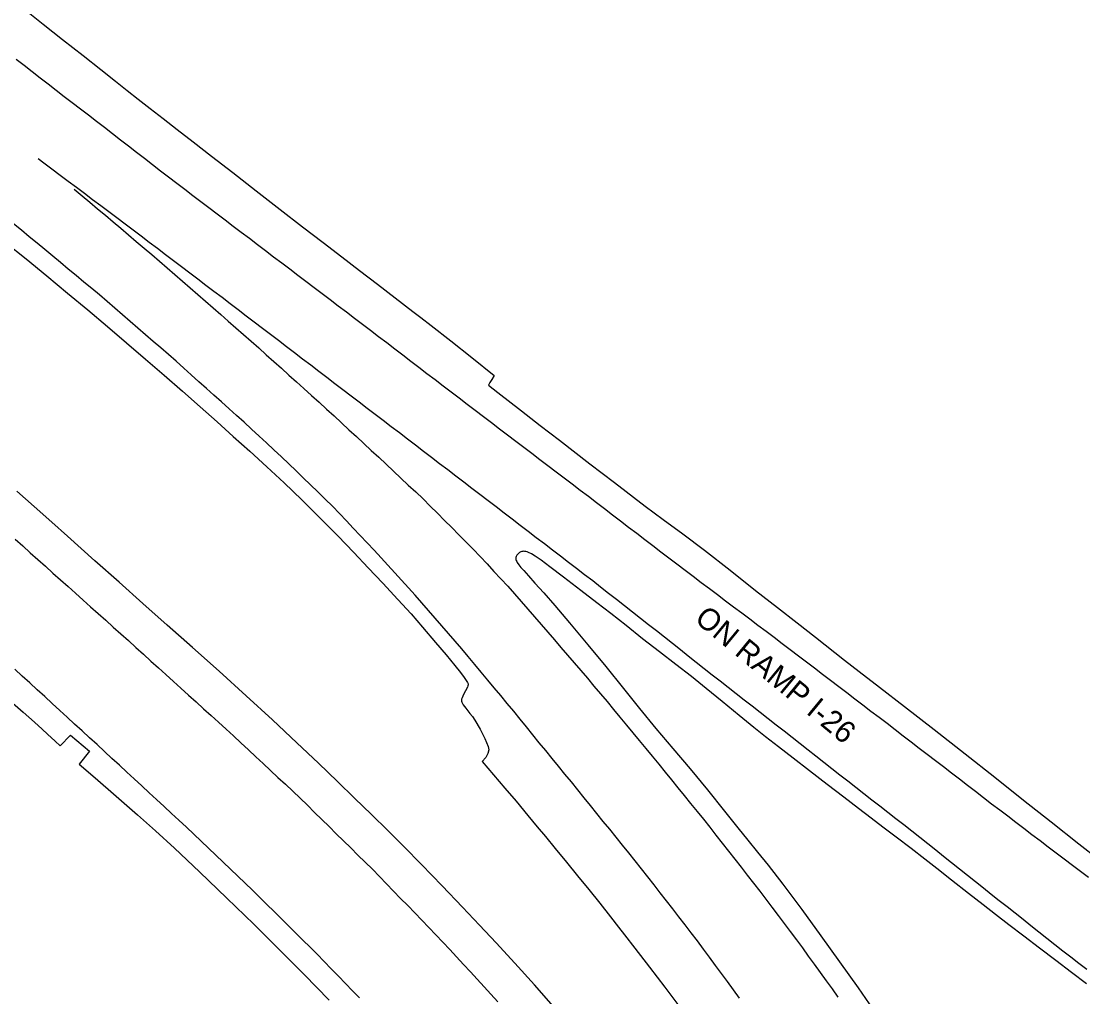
# Model space of a CAD drawing. Extents: x 1948091 to 1975253, y 787267 to 823306.
# Drawn here: x 1968847.6 to 1969109.2, y 799121.5 to 799361.9 of the extents above; entities that cross this region are included whole.
import ezdxf

# ---------------------------------------------------------------- set-up
doc = ezdxf.new("R2010")
doc.units = 0
for name, color, linetype in [('RD_EX_Pavement_Markings', 7, 'Continuous'), ('RD_EX_Road', 7, 'Continuous'), ('RD_TX_RoadID', 7, 'Continuous')]:
    doc.layers.add(name, color=color, linetype=linetype)

msp = doc.modelspace()

# ---------------------------------------------------------------- linework, layer by layer
at = {"layer": 'RD_EX_Pavement_Markings'}
for points in [[(1968846.31, 799352.62), (1968848.29, 799351.09), (1968850.27, 799349.55), (1968852.24, 799348.02), (1968854.22, 799346.49), (1968856.19, 799344.96), (1968858.17, 799343.43), (1968860.15, 799341.9), (1968862.13, 799340.37), (1968864.1, 799338.84), (1968866.08, 799337.32), (1968868.06, 799335.79), (1968870.04, 799334.26), (1968872.02, 799332.73), (1968874, 799331.21), (1968875.98, 799329.68), (1968877.96, 799328.15), (1968879.94, 799326.62), (1968881.92, 799325.1), (1968883.9, 799323.57), (1968885.88, 799322.05), (1968887.87, 799320.53), (1968889.86, 799319.02), (1968891.85, 799317.51), (1968893.84, 799316), (1968895.84, 799314.49), (1968897.83, 799312.98), (1968899.82, 799311.47), (1968901.81, 799309.95), (1968903.8, 799308.44), (1968905.79, 799306.93), (1968907.78, 799305.42), (1968909.77, 799303.91), (1968911.77, 799302.4), (1968913.76, 799300.88), (1968915.75, 799299.37), (1968917.74, 799297.86), (1968919.73, 799296.35), (1968921.72, 799294.84), (1968923.71, 799293.33), (1968925.71, 799291.82), (1968927.7, 799290.3), (1968929.69, 799288.79), (1968931.68, 799287.28), (1968933.67, 799285.77), (1968935.66, 799284.26), (1968937.65, 799282.74), (1968939.63, 799281.22), (1968941.62, 799279.7), (1968943.61, 799278.18), (1968945.59, 799276.67), (1968947.58, 799275.15), (1968949.56, 799273.63), (1968951.55, 799272.11), (1968953.54, 799270.59), (1968955.52, 799269.08), (1968957.51, 799267.56), (1968959.49, 799266.04), (1968961.48, 799264.52), (1968963.47, 799263.01), (1968965.46, 799261.5), (1968967.45, 799259.99), (1968969.44, 799258.47), (1968971.43, 799256.96), (1968973.42, 799255.45), (1968975.41, 799253.93), (1968977.4, 799252.42), (1968979.39, 799250.91), (1968981.38, 799249.39), (1968983.37, 799247.88), (1968985.36, 799246.37), (1968987.35, 799244.85), (1968989.34, 799243.33), (1968991.32, 799241.82), (1968993.31, 799240.3), (1968995.3, 799238.78), (1968997.28, 799237.26), (1968999.27, 799235.74), (1969001.26, 799234.23), (1969003.24, 799232.71), (1969005.23, 799231.19), (1969007.22, 799229.67), (1969009.2, 799228.16), (1969011.19, 799226.65), (1969013.19, 799225.14), (1969015.19, 799223.64), (1969017.18, 799222.13), (1969019.18, 799220.63), (1969021.18, 799219.12), (1969023.17, 799217.62), (1969025.17, 799216.11), (1969027.16, 799214.61), (1969029.16, 799213.1), (1969031.16, 799211.6), (1969033.15, 799210.09), (1969035.15, 799208.59), (1969037.14, 799207.07), (1969039.13, 799205.56), (1969041.12, 799204.04), (1969043.1, 799202.53), (1969045.09, 799201.01), (1969047.08, 799199.5), (1969049.07, 799197.98), (1969051.06, 799196.46), (1969053.05, 799194.95), (1969055.03, 799193.43), (1969057.02, 799191.92), (1969059.01, 799190.4), (1969061, 799188.89), (1969062.98, 799187.36), (1969064.96, 799185.84), (1969066.94, 799184.32), (1969068.93, 799182.79), (1969070.91, 799181.27), (1969072.89, 799179.74), (1969074.87, 799178.22), (1969076.85, 799176.7), (1969078.84, 799175.17), (1969080.82, 799173.65), (1969082.8, 799172.13), (1969084.78, 799170.6), (1969086.76, 799169.08), (1969088.75, 799167.56), (1969090.74, 799166.05), (1969092.73, 799164.54), (1969094.72, 799163.02), (1969096.71, 799161.51), (1969098.7, 799160), (1969100.69, 799158.48), (1969102.68, 799156.97), (1969104.67, 799155.45), (1969106.66, 799153.95), (1969108.67, 799152.46), (1969110.68, 799150.96)], [(1969110.25, 799128.18), (1969108.26, 799129.7), (1969106.29, 799131.24), (1969104.32, 799132.77), (1969102.35, 799134.31), (1969100.38, 799135.85), (1969098.41, 799137.39), (1969096.45, 799138.94), (1969094.5, 799140.5), (1969092.54, 799142.06), (1969090.59, 799143.62), (1969088.63, 799145.17), (1969086.68, 799146.73), (1969084.72, 799148.29), (1969082.76, 799149.85), (1969080.81, 799151.4), (1969078.85, 799152.96), (1969076.9, 799154.52), (1969074.94, 799156.08), (1969072.99, 799157.63), (1969071.03, 799159.19), (1969069.07, 799160.75), (1969067.11, 799162.29), (1969065.14, 799163.83), (1969063.17, 799165.37), (1969061.2, 799166.91), (1969059.23, 799168.45), (1969057.26, 799169.99), (1969055.29, 799171.53), (1969053.32, 799173.07), (1969051.35, 799174.61), (1969049.38, 799176.15), (1969047.41, 799177.69), (1969045.44, 799179.23), (1969043.47, 799180.77), (1969041.5, 799182.31), (1969039.53, 799183.85), (1969037.56, 799185.39), (1969035.59, 799186.92), (1969033.62, 799188.46), (1969031.65, 799190), (1969029.68, 799191.54), (1969027.71, 799193.08), (1969025.74, 799194.62), (1969023.77, 799196.16), (1969021.81, 799197.7), (1969019.84, 799199.25), (1969017.88, 799200.8), (1969015.92, 799202.35), (1969013.96, 799203.91), (1969012, 799205.46), (1969010.04, 799207.01), (1969008.08, 799208.56), (1969006.12, 799210.1), (1969004.15, 799211.65), (1969002.18, 799213.19), (1969000.22, 799214.74), (1968998.25, 799216.28), (1968996.28, 799217.82), (1968994.32, 799219.37), (1968992.35, 799220.91), (1968990.38, 799222.45), (1968988.42, 799224), (1968986.43, 799225.52), (1968984.45, 799227.04), (1968982.46, 799228.56), (1968980.48, 799230.08), (1968978.49, 799231.6), (1968976.51, 799233.12), (1968974.52, 799234.64), (1968972.54, 799236.15), (1968970.55, 799237.67), (1968968.57, 799239.19), (1968966.58, 799240.71), (1968964.6, 799242.23), (1968962.62, 799243.75), (1968960.63, 799245.27), (1968958.65, 799246.79), (1968956.66, 799248.31), (1968954.68, 799249.83), (1968952.69, 799251.35), (1968950.7, 799252.87), (1968948.72, 799254.38), (1968946.73, 799255.9), (1968944.74, 799257.42), (1968942.75, 799258.94), (1968940.77, 799260.45), (1968938.78, 799261.97), (1968936.79, 799263.49), (1968934.81, 799265), (1968932.82, 799266.52), (1968930.83, 799268.04), (1968928.85, 799269.55), (1968926.86, 799271.07), (1968924.87, 799272.59), (1968922.88, 799274.1), (1968920.9, 799275.62), (1968918.91, 799277.14), (1968916.92, 799278.66), (1968914.94, 799280.17), (1968912.95, 799281.69), (1968910.96, 799283.21), (1968908.98, 799284.72), (1968906.99, 799286.24), (1968905, 799287.76), (1968903.01, 799289.27), (1968901.03, 799290.79), (1968899.04, 799292.31), (1968897.05, 799293.82), (1968895.06, 799295.33), (1968893.07, 799296.84), (1968891.07, 799298.35), (1968889.08, 799299.87), (1968887.09, 799301.38), (1968885.1, 799302.89), (1968883.11, 799304.4), (1968881.12, 799305.91), (1968879.12, 799307.42), (1968877.13, 799308.93), (1968875.14, 799310.44), (1968873.15, 799311.95), (1968871.16, 799313.46), (1968869.15, 799314.96), (1968867.15, 799316.46), (1968865.15, 799317.96), (1968863.15, 799319.46), (1968861.15, 799320.95), (1968859.15, 799322.45), (1968857.15, 799323.95), (1968855.14, 799325.45), (1968853.14, 799326.95), (1968851.72, 799328.01)], [(1968860.62, 799320.53), (1968862.54, 799318.93), (1968864.46, 799317.32), (1968866.37, 799315.72), (1968868.29, 799314.11), (1968870.21, 799312.51), (1968872.12, 799310.9), (1968874.03, 799309.29), (1968875.93, 799307.66), (1968877.83, 799306.04), (1968879.73, 799304.41), (1968881.63, 799302.79), (1968883.53, 799301.16), (1968885.43, 799299.54), (1968887.33, 799297.91), (1968889.21, 799296.26), (1968891.09, 799294.61), (1968892.97, 799292.96), (1968894.84, 799291.31), (1968896.72, 799289.66), (1968898.6, 799288.01), (1968900.47, 799286.36), (1968902.35, 799284.71), (1968904.23, 799283.06), (1968906.11, 799281.41), (1968907.97, 799279.74), (1968909.83, 799278.07), (1968911.69, 799276.39), (1968913.54, 799274.72), (1968915.4, 799273.05), (1968917.26, 799271.38), (1968919.12, 799269.7), (1968920.97, 799268.03), (1968922.83, 799266.36), (1968924.67, 799264.66), (1968926.5, 799262.96), (1968928.34, 799261.26), (1968930.17, 799259.56), (1968932, 799257.86), (1968933.83, 799256.16), (1968935.67, 799254.46), (1968937.5, 799252.76), (1968939.32, 799251.05), (1968941.15, 799249.34), (1968942.97, 799247.63), (1968944.8, 799245.92), (1968946.61, 799244.2), (1968948.38, 799242.44), (1968950.15, 799240.67), (1968951.93, 799238.91), (1968953.7, 799237.15), (1968955.45, 799235.36), (1968957.2, 799233.58), (1968958.95, 799231.79), (1968960.7, 799230.01), (1968962.4, 799228.17), (1968964.09, 799226.34), (1968965.78, 799224.5), (1968967.48, 799222.66), (1968969.15, 799220.8), (1968970.79, 799218.91), (1968972.43, 799217.03), (1968974.07, 799215.14), (1968975.71, 799213.26), (1968977.36, 799211.37), (1968978.99, 799209.47), (1968980.61, 799207.57), (1968982.24, 799205.67), (1968983.86, 799203.77), (1968985.49, 799201.87), (1968987.11, 799199.98), (1968988.73, 799198.08), (1968990.36, 799196.18), (1968991.96, 799194.26), (1968993.55, 799192.33), (1968995.14, 799190.4), (1968996.74, 799188.47), (1968998.33, 799186.55), (1968999.92, 799184.62), (1969001.51, 799182.69), (1969003.1, 799180.76), (1969004.69, 799178.83), (1969006.26, 799176.89), (1969007.84, 799174.95), (1969009.41, 799173), (1969010.99, 799171.06), (1969012.56, 799169.12), (1969014.14, 799167.18), (1969015.72, 799165.24), (1969017.28, 799163.29), (1969018.82, 799161.32), (1969020.36, 799159.36), (1969021.9, 799157.39), (1969023.45, 799155.42), (1969024.99, 799153.45), (1969026.53, 799151.48), (1969028.07, 799149.52), (1969029.6, 799147.53), (1969031.1, 799145.54), (1969032.61, 799143.54), (1969034.11, 799141.55), (1969035.62, 799139.55), (1969037.12, 799137.55), (1969038.63, 799135.56), (1969040.12, 799133.55), (1969041.58, 799131.52), (1969043.04, 799129.5), (1969044.5, 799127.47), (1969045.96, 799125.44), (1969047.42, 799123.41), (1969048.88, 799121.38)], [(1969024.59, 799121.15), (1969023.15, 799123.2), (1969021.68, 799125.22), (1969020.19, 799127.23), (1969018.7, 799129.23), (1969017.21, 799131.24), (1969015.71, 799133.25), (1969014.22, 799135.25), (1969012.73, 799137.26), (1969011.21, 799139.24), (1969009.67, 799141.21), (1969008.14, 799143.19), (1969006.6, 799145.16), (1969005.07, 799147.14), (1969003.54, 799149.11), (1969002, 799151.08), (1969000.46, 799153.05), (1968998.89, 799155), (1968997.32, 799156.95), (1968995.75, 799158.89), (1968994.18, 799160.84), (1968992.61, 799162.78), (1968991.04, 799164.73), (1968989.47, 799166.67), (1968987.9, 799168.62), (1968986.33, 799170.56), (1968984.75, 799172.5), (1968983.17, 799174.44), (1968981.59, 799176.37), (1968980.01, 799178.31), (1968978.43, 799180.25), (1968976.85, 799182.18), (1968975.27, 799184.12), (1968973.69, 799186.06), (1968972.11, 799187.99), (1968970.53, 799189.93), (1968968.95, 799191.87), (1968967.35, 799193.8), (1968965.75, 799195.72), (1968964.15, 799197.64), (1968962.55, 799199.56), (1968960.96, 799201.48), (1968959.36, 799203.4), (1968957.76, 799205.32), (1968956.14, 799207.23), (1968954.5, 799209.12), (1968952.87, 799211.01), (1968951.23, 799212.9), (1968949.6, 799214.79), (1968947.96, 799216.68), (1968946.33, 799218.57), (1968944.67, 799220.45), (1968942.99, 799222.3), (1968941.3, 799224.14), (1968939.62, 799225.99), (1968937.94, 799227.84), (1968936.25, 799229.69), (1968934.57, 799231.53), (1968932.86, 799233.36), (1968931.14, 799235.17), (1968929.42, 799236.99), (1968927.7, 799238.8), (1968925.98, 799240.62), (1968924.26, 799242.43), (1968922.47, 799244.17), (1968920.67, 799245.91), (1968918.88, 799247.65), (1968917.08, 799249.39), (1968915.29, 799251.13), (1968913.49, 799252.87), (1968911.68, 799254.6), (1968909.84, 799256.29), (1968908.01, 799257.99), (1968906.17, 799259.68), (1968904.33, 799261.38), (1968902.5, 799263.08), (1968900.64, 799264.75), (1968898.78, 799266.42), (1968896.92, 799268.09), (1968895.06, 799269.76), (1968893.2, 799271.43), (1968891.34, 799273.1), (1968889.48, 799274.78), (1968887.62, 799276.45), (1968885.76, 799278.12), (1968883.88, 799279.76), (1968881.99, 799281.4), (1968880.1, 799283.03), (1968878.21, 799284.67), (1968876.31, 799286.3), (1968874.42, 799287.94), (1968872.53, 799289.57), (1968870.64, 799291.21), (1968868.75, 799292.84), (1968866.85, 799294.47), (1968864.93, 799296.06), (1968863, 799297.66), (1968861.08, 799299.26), (1968859.16, 799300.86), (1968857.23, 799302.45), (1968855.31, 799304.05), (1968853.39, 799305.65), (1968851.47, 799307.25), (1968849.54, 799308.84), (1968847.6, 799310.41), (1968845.65, 799311.99)], [(1968846.06, 799234.27), (1968847.92, 799232.61), (1968849.78, 799230.94), (1968851.64, 799229.27), (1968853.5, 799227.61), (1968855.37, 799225.94), (1968857.23, 799224.27), (1968859.09, 799222.61), (1968860.95, 799220.94), (1968862.81, 799219.27), (1968864.67, 799217.61), (1968866.54, 799215.94), (1968868.4, 799214.28), (1968870.26, 799212.61), (1968872.12, 799210.94), (1968873.98, 799209.28), (1968875.84, 799207.61), (1968877.69, 799205.93), (1968879.54, 799204.25), (1968881.39, 799202.57), (1968883.24, 799200.89), (1968885.09, 799199.21), (1968886.94, 799197.54), (1968888.79, 799195.86), (1968890.64, 799194.18), (1968892.5, 799192.5), (1968894.35, 799190.82), (1968896.2, 799189.14), (1968898.05, 799187.47), (1968899.89, 799185.78), (1968901.71, 799184.07), (1968903.54, 799182.37), (1968905.37, 799180.67), (1968907.2, 799178.97), (1968909.03, 799177.26), (1968910.85, 799175.56), (1968912.68, 799173.86), (1968914.51, 799172.16), (1968916.32, 799170.44), (1968918.1, 799168.69), (1968919.88, 799166.93), (1968921.66, 799165.18), (1968923.44, 799163.43), (1968925.22, 799161.68), (1968927, 799159.92), (1968928.78, 799158.17), (1968930.56, 799156.42), (1968932.33, 799154.66), (1968934.11, 799152.91), (1968935.85, 799151.12), (1968937.6, 799149.33), (1968939.34, 799147.54), (1968941.08, 799145.75), (1968942.83, 799143.96), (1968944.56, 799142.17), (1968946.29, 799140.37), (1968948.02, 799138.57), (1968949.76, 799136.77), (1968951.47, 799134.95), (1968953.17, 799133.12), (1968954.87, 799131.3), (1968956.57, 799129.47), (1968958.28, 799127.64), (1968959.98, 799125.81), (1968961.68, 799123.98), (1968963.35, 799122.13), (1968965.02, 799120.27)], [(1968930.96, 799121.2), (1968929.22, 799122.99), (1968927.48, 799124.78), (1968925.74, 799126.58), (1968923.99, 799128.37), (1968922.25, 799130.16), (1968920.51, 799131.95), (1968918.75, 799133.72), (1968916.98, 799135.48), (1968915.2, 799137.23), (1968913.42, 799138.99), (1968911.64, 799140.75), (1968909.87, 799142.5), (1968908.09, 799144.26), (1968906.31, 799146.01), (1968904.53, 799147.77), (1968902.73, 799149.49), (1968900.92, 799151.22), (1968899.11, 799152.94), (1968897.3, 799154.67), (1968895.5, 799156.39), (1968893.69, 799158.12), (1968891.88, 799159.84), (1968890.07, 799161.57), (1968888.26, 799163.29), (1968886.43, 799164.99), (1968884.6, 799166.68), (1968882.76, 799168.38), (1968880.93, 799170.08), (1968879.09, 799171.77), (1968877.26, 799173.47), (1968875.43, 799175.17), (1968873.59, 799176.86), (1968871.75, 799178.56), (1968869.91, 799180.25), (1968868.08, 799181.94), (1968866.24, 799183.63), (1968864.4, 799185.32), (1968862.56, 799187.01), (1968860.72, 799188.71), (1968858.88, 799190.4), (1968857.04, 799192.09), (1968855.19, 799193.78), (1968853.35, 799195.46), (1968851.5, 799197.15), (1968849.66, 799198.84), (1968847.82, 799200.52), (1968845.97, 799202.21)]]:
    msp.add_lwpolyline(points, dxfattribs=at)
at = {"layer": 'RD_EX_Road'}
for points in [[(1968849.26, 799364.16), (1968852.94, 799361.25), (1968857.77, 799357.44), (1968862.82, 799353.46), (1968867.16, 799350.04), (1968870.78, 799347.18), (1968873.68, 799344.88), (1968876.37, 799342.77), (1968879.31, 799340.46), (1968882.53, 799337.96), (1968886.01, 799335.25), (1968889.94, 799332.21), (1968894.5, 799328.67), (1968899.68, 799324.64), (1968905.5, 799320.13), (1968911.42, 799315.54), (1968916.9, 799311.3), (1968921.95, 799307.4), (1968926.56, 799303.85), (1968930.96, 799300.48), (1968935.34, 799297.11), (1968939.7, 799293.76), (1968944.06, 799290.42), (1968946.02, 799288.89), (1968948.57, 799286.93), (1968953.42, 799283.14), (1968958.6, 799279.05), (1968964.11, 799274.66), (1968963.55, 799273.61), (1968963.08, 799272.88), (1968962.72, 799272.22), (1968965.08, 799270.46), (1968970.89, 799265.91), (1968975.51, 799262.31), (1968980.21, 799258.68), (1968987.7, 799252.88), (1968993.78, 799248.22), (1969001.37, 799242.45), (1969005.81, 799239.11), (1969010.62, 799235.58), (1969016.02, 799231.53), (1969022.28, 799226.62), (1969028.55, 799221.65), (1969034, 799217.4), (1969038.86, 799213.63), (1969043.32, 799210.1), (1969050.49, 799204.45), (1969054.08, 799201.68), (1969059.09, 799197.83), (1969065.32, 799193.02), (1969072.59, 799187.38), (1969080.22, 799181.4), (1969087.56, 799175.59), (1969094.62, 799169.97), (1969101.4, 799164.59), (1969108.25, 799159.19), (1969113.1, 799155.39)], [(1968843.57, 799307.52), (1968848.75, 799303.37), (1968853.89, 799299.15), (1968858.98, 799294.95), (1968863.99, 799290.78), (1968868.83, 799286.68), (1968873.52, 799282.67), (1968878.16, 799278.67), (1968882.77, 799274.67), (1968887.28, 799270.75), (1968891.67, 799266.91), (1968895.84, 799263.21), (1968899.83, 799259.61), (1968903.9, 799255.94), (1968908.08, 799252.14), (1968912.35, 799248.16), (1968916.69, 799243.97), (1968921.12, 799239.59), (1968925.56, 799235.09), (1968929.55, 799230.97), (1968933.09, 799227.24), (1968936.7, 799223.4), (1968940.38, 799219.45), (1968943.64, 799215.84), (1968946.49, 799212.57), (1968949.69, 799208.83), (1968952.27, 799205.79), (1968954.45, 799203.15), (1968955.86, 799201.38), (1968956.76, 799200.18), (1968957.25, 799199.47), (1968957.55, 799198.97), (1968957.64, 799198.78), (1968957.69, 799198.6), (1968957.69, 799198.37), (1968957.65, 799198.1), (1968957.56, 799197.79), (1968957.06, 799196.9), (1968956.57, 799195.99), (1968956.21, 799195.2), (1968956.12, 799194.88), (1968956.09, 799194.63), (1968956.11, 799194.38), (1968956.18, 799194.11), (1968956.31, 799193.8), (1968956.5, 799193.46), (1968957.12, 799192.59), (1968958.14, 799191.35), (1968958.76, 799190.58), (1968959.38, 799189.67), (1968960.66, 799187.43), (1968961.8, 799185.11), (1968962.64, 799183.2), (1968962.8, 799182.33), (1968962.61, 799181.42), (1968962.06, 799180.47), (1968961.15, 799179.48), (1968966.76, 799172.94), (1968969.54, 799169.68), (1968972.46, 799166.18), (1968974.75, 799163.41), (1968976.76, 799160.96), (1968979.15, 799158.06), (1968981.94, 799154.67), (1968984.72, 799151.28), (1968987.44, 799147.94), (1968990.16, 799144.53), (1968992.81, 799141.16), (1968994.81, 799138.63), (1968996.3, 799136.75), (1968998.82, 799133.51), (1969002.44, 799128.78), (1969006.22, 799123.83), (1969010.16, 799118.6)], [(1968978.78, 799119.12), (1968974.05, 799124.47), (1968969.23, 799129.77), (1968964.63, 799134.75), (1968960.55, 799139.13), (1968956.33, 799143.61), (1968951.29, 799148.87), (1968946.22, 799154.11), (1968941.89, 799158.5), (1968937.91, 799162.47), (1968933.87, 799166.45), (1968929.75, 799170.46), (1968925.52, 799174.57), (1968920.86, 799179.03), (1968915.5, 799184.11), (1968909.51, 799189.71), (1968903, 799195.7), (1968896.31, 799201.76), (1968889.78, 799207.56), (1968883.5, 799213.11), (1968877.54, 799218.42), (1968871.68, 799223.66), (1968865.72, 799228.98), (1968858.98, 799234.98), (1968855.06, 799238.48), (1968850.78, 799242.3), (1968846.48, 799246.13)], [(1969110.13, 799124.68), (1969106.42, 799127.47), (1969102.55, 799130.41), (1969098.55, 799133.46), (1969094.68, 799136.43), (1969091.01, 799139.25), (1969087.72, 799141.78), (1969084.71, 799144.11), (1969081.07, 799146.96), (1969076.86, 799150.27), (1969073.25, 799153.11), (1969070.26, 799155.44), (1969066.92, 799158.01), (1969063.21, 799160.83), (1969059.93, 799163.32), (1969057.11, 799165.49), (1969053.94, 799167.92), (1969050.31, 799170.71), (1969046.24, 799173.83), (1969041.85, 799177.19), (1969037.81, 799180.3), (1969034.23, 799183.09), (1969031.04, 799185.57), (1969028.11, 799187.89), (1969024.53, 799190.79), (1969020.32, 799194.25), (1969016.38, 799197.48), (1969012.77, 799200.42), (1969008.95, 799203.41), (1969004.86, 799206.54), (1969000.73, 799209.75), (1968996.65, 799213), (1968992.92, 799215.94), (1968989.46, 799218.6), (1968985.52, 799221.62), (1968981.2, 799224.93), (1968977.89, 799227.46), (1968975.75, 799229.07), (1968974.28, 799230.09), (1968973.36, 799230.64), (1968972.61, 799230.99), (1968972.29, 799231.12), (1968971.98, 799231.22), (1968971.7, 799231.27), (1968971.43, 799231.29), (1968971.17, 799231.28), (1968970.94, 799231.23), (1968970.74, 799231.18), (1968970.56, 799231.1), (1968970.41, 799231.02), (1968970.26, 799230.9), (1968969.93, 799230.54), (1968969.73, 799230.3), (1968969.57, 799230.04), (1968969.47, 799229.79), (1968969.44, 799229.53), (1968969.48, 799229.28), (1968969.57, 799229.03), (1968969.69, 799228.77), (1968969.84, 799228.5), (1968970.24, 799227.95), (1968970.75, 799227.32), (1968971.43, 799226.54), (1968972.56, 799225.28), (1968974.18, 799223.46), (1968976.34, 799221.04), (1968979.08, 799217.92), (1968982.74, 799213.62), (1968987.21, 799208.25), (1968991.63, 799202.87), (1968996.04, 799197.45), (1968999.99, 799192.58), (1969004.03, 799187.63), (1969008.18, 799182.67), (1969012.44, 799177.66), (1969016.73, 799172.47), (1969020.91, 799167.26), (1969024.23, 799163.11), (1969026.69, 799160.05), (1969029.09, 799157.12), (1969031.69, 799153.94), (1969035.32, 799149.23), (1969039.96, 799142.98), (1969044.67, 799136.55), (1969049.29, 799130.14), (1969053.87, 799123.67), (1969058.42, 799117.1)], [(1968844.14, 799195.03), (1968848.01, 799191.66), (1968850.81, 799189.17), (1968852.75, 799187.42), (1968854.06, 799186.21), (1968855.92, 799184.47), (1968857.14, 799183.34), (1968859.74, 799185.95), (1968864.4, 799182.03), (1968861.86, 799178.85), (1968865.8, 799175.43), (1968870.93, 799170.96), (1968876.23, 799166.32), (1968880.65, 799162.4), (1968885.34, 799158.1), (1968891.49, 799152.32), (1968898.27, 799145.83), (1968904.87, 799139.4), (1968911.24, 799133.08), (1968917.33, 799126.96), (1968923.47, 799120.64)]]:
    msp.add_lwpolyline(points, dxfattribs=at)

# ---------------------------------------------------------------- texts
at = {"layer": 'RD_TX_RoadID'}
msp.add_text('ON RAMP I-26', height=5.4, rotation=320.5238, dxfattribs=at).set_placement((1969013.26, 799214.15))

doc.saveas('drawing.dxf')
